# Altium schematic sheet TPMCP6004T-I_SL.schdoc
size 127 x 101 mm
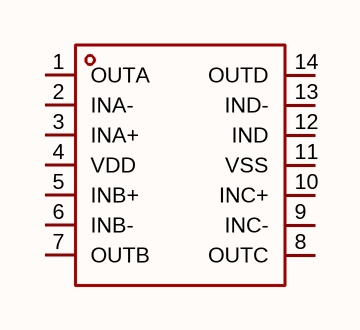
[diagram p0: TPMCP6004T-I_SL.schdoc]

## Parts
U?  tpmcp6004t-i/sl  [SOIC-14_L8.7-W3.9-P1.27-LS6.0-BL]  (value not drawn)

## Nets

Not connected (* = marked no-connect by the designer): U? 1(OUTA) 2(INA-) 3(INA+) 4(VDD) 5(INB+) 6(INB-) 7(OUTB) 8(OUTC) 9(INC-) 10(INC+) 11(VSS) 12(IND) 13(IND-) 14(OUTD)

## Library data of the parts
U? = tpmcp6004t-i/sl: 放大器数:2;轨到轨:轨到轨输入,轨到轨输出;增益带宽积(GBW):1MHz;输入失调电压(Vos):5mV;压摆率(SR):600V/ms;输入偏置电流(Ib):10pA;; Manufacturer: TECH PUBLIC(台舟); AddInBom: yes; ModelId: 8dbf5b715d42428c85558507ae5a252b; ModelName: SOIC-14_L8.6-W3.9-H1.8-LS6.0-P1.27; ModelTransform: 338.583,236.22,0,0,0,0,0,0.001,0; Number of Channels: 2; Maximum Power Supply Range (Vdd-Vss): 5.5V; Gain Bandwidth Product: 1MHz; Vos - Input Offset Voltage: 5mV; Input Offset Voltage Drift(Vos TC): 2uV/℃; Ib - Input Bias Current: 10pA; Input Voltage Noise Density: 20nV/√Hz@10kHz; Common Mode Rejection Ratio(CMRR): 80dB; Quiescent Current: 40uA; Output Current: 20mA; Single supply: 2.2V~5.5V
